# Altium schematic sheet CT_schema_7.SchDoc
size 287 x 160 mm
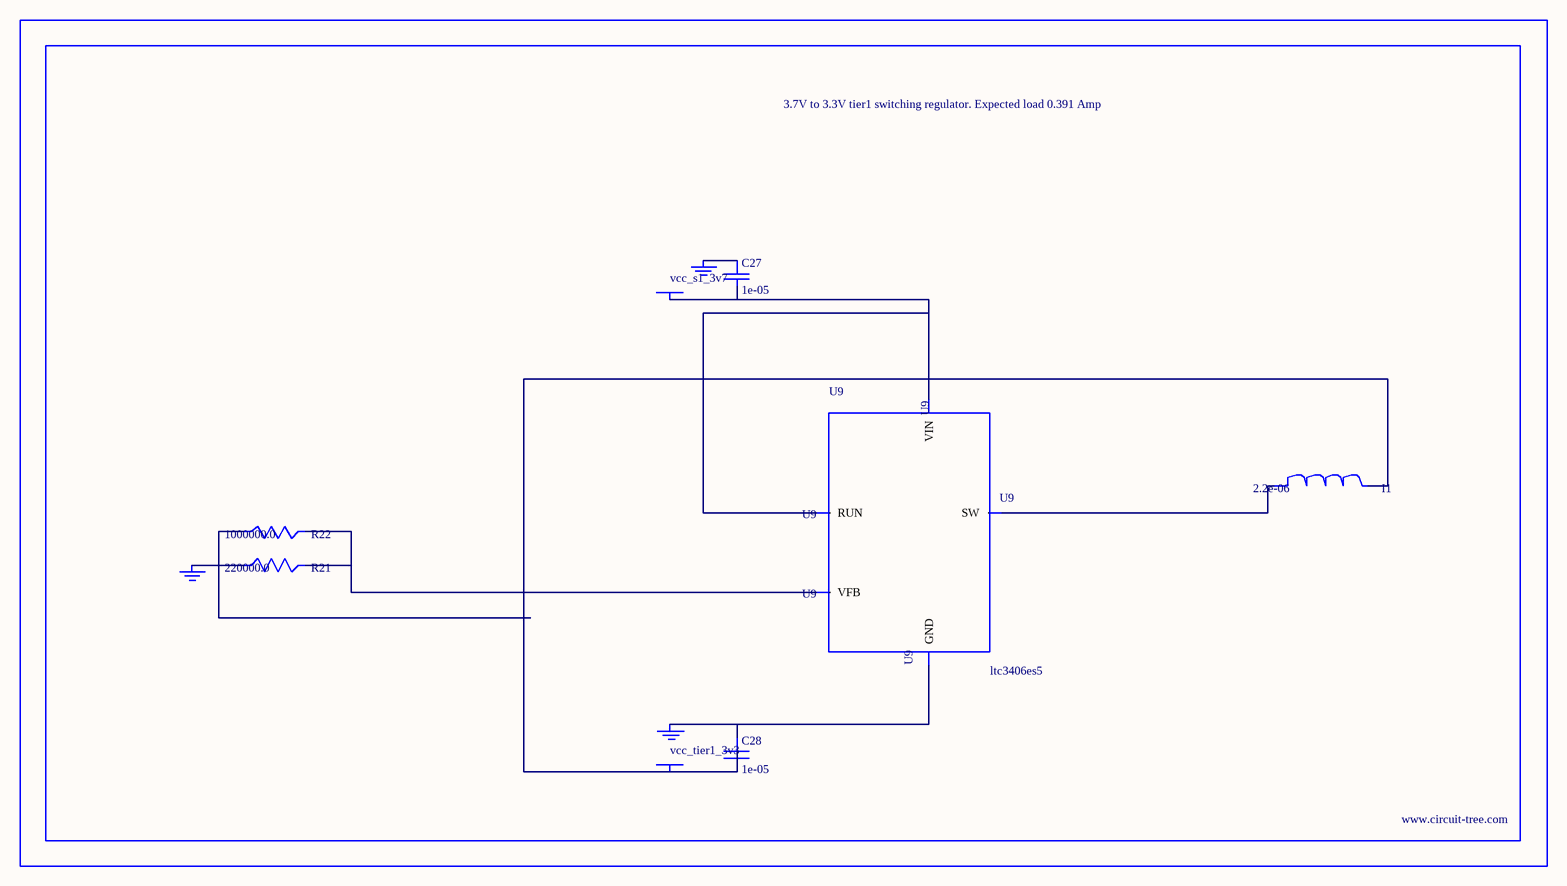
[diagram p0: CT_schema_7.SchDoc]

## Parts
BORDER6  (no value)
C27  1e-05  [C0805]
C28  1e-05  [C0805]
GND_INSTANCE_6_0  (no value)
GND_INSTANCE_6_1  (no value)
GND_INSTANCE_6_2  (no value)
I1  2.2e-06  [L0805]
POWER_INSTANCE_6_0  vcc_tier1_3v3
POWER_INSTANCE_6_1  vcc_s1_3v7
R21  220000.0  [R0603]
R22  1000000.0  [R0603]
U9  ltc3406es5  [TSOT-23-5]

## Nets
NetC27_1: C27.1 GND_INSTANCE_6_1.0(GND)
NetC27_2: C27.2 POWER_INSTANCE_6_1.0(PWR) U9.1(RUN) U9.4(VIN)
NetC28_1: C28.1 GND_INSTANCE_6_0.0(GND) U9.2(GND)
NetC28_2: C28.2 I1.2 POWER_INSTANCE_6_0.0(PWR) R22.1
NetGND_INSTANCE_6_2_0: GND_INSTANCE_6_2.0(GND) R21.1
NetI1_1: I1.1 U9.3(SW)
NetR21_2: R21.2 R22.2 U9.5(VFB)

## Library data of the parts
BORDER6 = BORDER_PAGE6
C27 C28 = C0805C106K8RACTU
GND_INSTANCE_6_0-GND_INSTANCE_6_2 = GND
I1 = L0805C2R2MDWIT
POWER_INSTANCE_6_0 POWER_INSTANCE_6_1 = PWR
R21 = RC0603JR-07220KL
R22 = RC0603JR-071ML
